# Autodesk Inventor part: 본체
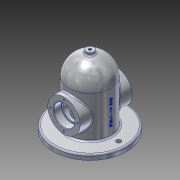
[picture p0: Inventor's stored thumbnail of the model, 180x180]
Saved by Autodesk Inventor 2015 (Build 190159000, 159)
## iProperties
Created: 2019-11
Part Number: 본체
Material: 알루미늄 6061
Document SubType Name: Modeling
Designer: Lineart
Density: 2.7 g/cm^3
Appearance: 알루미늄 - 평지
Mass: 1106.46 g
Surface Area: 885.034 cm^2
Volume: 409.799 cm^3
Author: Lineart
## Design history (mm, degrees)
sketch "스케치1"
  geometry: L1 (0, 0)-(-70, 0); L2 (-70, 0)-(-70, 10); L3 (-70, 10)-(-40, 10); L4 (-40, 10)-(-40, 90); L5 (0, 0)-(0, 130); A1 r 40 centre (0, 90) between (0, 130) and (-40, 90)
  constraints: 10 end point, 3 perpendicular, 2 point on circle, 1 centre point, 1 horizontal, 1 point on line, 1 vertical, 1 vertical alignment
  dimensions: "d0" = 70 distance of L1.start L1.end; "d1" = 10 distance of L1.end L2.end; "d2" = 40 distance between parallel lines of L5 L4; "d3" = 40 radius of A1; "d4" = 130 distance of L1.start L5.end
revolve "회전1" sketch "스케치1" stored, may be unused: angle "d5" = 90 deg
sketch "스케치2"
  geometry: C1 r 31 at (0, 50); A1 r 40 centre (0, 90) between (40, 90) and (-40, 90) reference; 1 further point
  constraints: 1 centre point, 1 vertical alignment
  dimensions: "d6" = 62 diameter of C1; "d7" = 50 distance of point (0, 0) C1.centre
extrude "돌출1" join sketch "스케치2" stored distance "d8" = 100; taper "d9" = 0 deg
sketch "스케치4"
  geometry: L1 (0, 0)-(-30, 0); L2 (70, 0)-(-70, 0) reference; L3 (-30, 0)-(-30, 90); L4 (40, 90)-(-40, 90) reference; L5 (0, 0)-(0, 120); A1 r 40 centre (0, 90) between (40, 90) and (-40, 90) reference; A2 r 30 centre (0, 90) between (0, 120) and (-30, 90)
  constraints: 6 end point, 2 point on circle, 2 point on line, 1 centre point, 1 coincident, 1 perpendicular, 1 vertical
  dimensions: "d13" = 30 distance of L1.start L1.end
revolve "회전2" sketch "스케치4" stored, may be unused: angle "d14" = 90 deg
hole "구멍1" diameter "d17" = 33; stored, may be unused: countersink angle "d21" = 90 deg, drill point angle "d23" = 118 deg; dims "d15" = 10, "d16" = 10, "d18" = 6, "d19" = 40, "d20" = 15, "d22" = 8
sketch "스케치5"
  geometry: C1 r 16.5 at (0, 0) reference; C2 r 20 at (0, 0); 1 further point
  constraints: 1 centre point, 1 coincident
  dimensions: "d24" = 40 diameter of C2
extrude "돌출2" cut sketch "스케치5" distance "d25" = 15; taper "d26" = 0 deg
node "작업 평면1"
sketch "스케치6"
  geometry: C1 r 7.5 at (0, 0); 1 further point
  constraints: 1 centre point, 1 coincident
  dimensions: "d28" = 15 diameter of C1
extrude "돌출3" join sketch "스케치6" stored distance "d29" = 15; taper "d30" = 0 deg
hole "구멍2" diameter "d33" = 5.188; stored, may be unused: countersink angle "d37" = 90 deg, drill point angle "d39" = 118 deg; dims "d31" = 10, "d32" = 10, "d34" = 12, "d35" = 40, "d36" = 15, "d38" = 16
sketch "스케치7"
  geometry: L1 (0, 0)-(0, -26); L2 (0, 0)-(26, 0); L3 (0, 0)-(0, 26); L4 (0, 0)-(-26, 0); C1 r 16.5 at (0, 0) reference; 1 further point
  constraints: 8 end point, 2 coincident, 1 vertical, 11 other
  dimensions: "d40" = 26 distance of L1.start L1.end; "d43" = 360 deg dimension on L1.start L1.end (derived)
hole "구멍3" sketch "스케치7" at (-26, 0), (0, 26), (0, -26), (26, 0) diameter "d45" = 3.242; stored, may be unused: countersink angle "d49" = 90 deg, drill point angle "d51" = 118 deg; dims "d46" = 8, "d47" = 40, "d48" = 15, "d50" = 10
fillet "모깎기1" dims "d52" = 3
sketch "스케치8"
  geometry: L1 (0, 0)-(-55, 0); L2 (0, 0)-(55, 0); C1 r 4.5 at (-55, 0); C2 r 4.5 at (55, 0)
  constraints: 4 end point, 2 centre point, 2 coincident, 2 horizontal
  dimensions: "d53" = 55 distance of L1.start L1.end; "d54" = 9 diameter of C1; "d55" = 55 distance of L1.start L2.end; "d56" = 9 diameter of C2
extrude "돌출4" cut sketch "스케치8" stored distance "d57" = 15; taper "d58" = 0 deg
node "작업 평면2"
sketch "스케치9"
  geometry: L1 (70, 0)-(-70, 0) reference; 3 further points
  constraints: 1 midpoint, 1 vertical alignment, 1 other
  dimensions: "d60" = 50 distance from line of L1 point (0, 50)
feature "엠보싱1" sketch "스케치9" dims "d0" = 70, "d1" = 10, "d2" = 40, "d3" = 40, "d4" = 130, "d61" = 0.5, "d62" = 0
fillet "모깎기2" dims "d63" = 0.3
chamfer "모따기1" distance "d64" = 1; stored, may be unused: second distance "d65" = 2, angle "d66" = 45 deg
node "솔리드1"
mirror "대칭1"
other parameters: "d27" = -135
